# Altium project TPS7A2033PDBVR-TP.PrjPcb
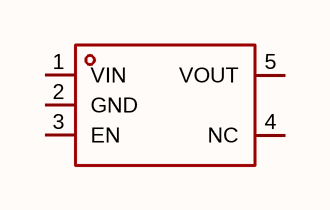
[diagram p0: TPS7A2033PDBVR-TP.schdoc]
1 sheet, 1 parts. Net scope: global (net labels, ports and power ports of the same name join across sheets).

## Sheet TPS7A2033PDBVR-TP.schdoc
size 127 x 101 mm

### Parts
U?  tps7a2033pdbvr-tp  [SOT-23-5_L2.9-W1.6-P0.95-LS2.8-BL]  (value not drawn)

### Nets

Not connected (* = marked no-connect by the designer): U? 1(VIN) 2(GND) 3(EN) 4(NC) 5(VOUT)

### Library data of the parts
U? = tps7a2033pdbvr-tp: 输出极性:正极;工作电压:5.5V;输出电压:3.3V;输出电流:300mA;电源纹波抑制比(PSRR):75dB@(1kHz);输出类型:固定;; Manufacturer: TECH PUBLIC(台舟); AddInBom: yes; ModelId: 018c57e721114987ae90467fe9f1d259; ModelTransform: 114.96,110.236,0,0,0,0,0,0,0; Output Configuration: 正极; Voltage - Supply: 5.5V; Output Voltage: 3.3V; Output Current: 300mA; Voltage Dropout: 180uV@(300mA); standby current: 2uA; Output Type: 固定; Number of Outputs: 1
